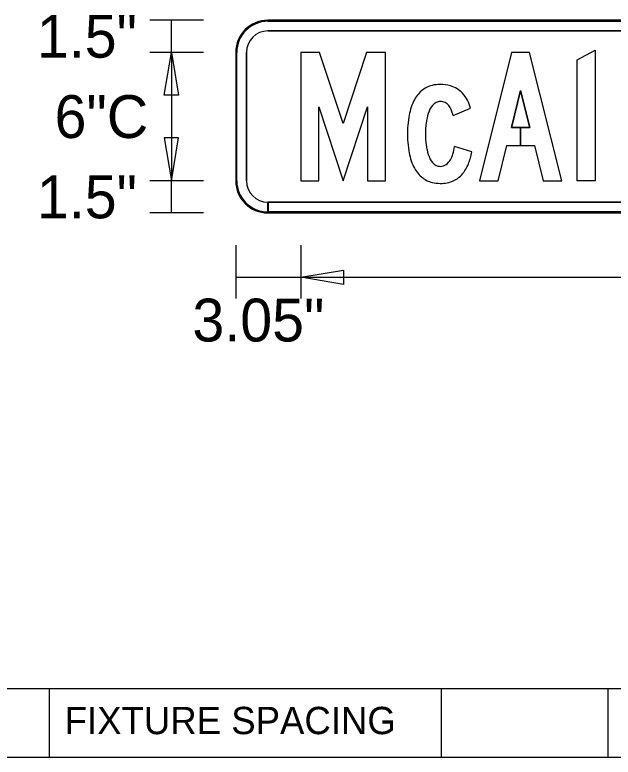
# Model space of a CAD drawing. Extents: x -875 to -645, y -2221 to -2162.
# Drawn here: x -774.222 to -771.896, y -2206.764 to -2203.876 of the extents above; entities that cross this region are included whole.
import ezdxf

# ---------------------------------------------------------------- set-up
doc = ezdxf.new("R2010")
doc.units = 0
for name, color, linetype in [('PlotBorder_dp', 7, 'Continuous'), ('SheetBorder_dp', 7, 'Continuous'), ('SheetLines_dp', 7, 'Continuous'), ('SheetLinesMisc2_dp', 7, 'Continuous'), ('TextMinor', 7, 'Continuous')]:
    doc.layers.add(name, color=color, linetype=linetype)

msp = doc.modelspace()

# ---------------------------------------------------------------- linework, layer by layer
at = {"layer": 'PlotBorder_dp'}
for p, q in [((-769.4881, -2203.8965), (-773.2381, -2203.8965)), ((-773.2381, -2203.9381), (-769.4881, -2203.9381)), ((-773.3631, -2204.0215), (-773.3631, -2204.5215)), ((-773.3215, -2204.5215), (-773.3215, -2204.0215)), ((-772.5183, -2204.2671), (-772.4509, -2204.2387)), ((-772.6906, -2204.2737), (-772.6945, -2204.3064)), ((-772.6945, -2204.3715), (-772.6906, -2204.4042)), ((-772.4456, -2204.4091), (-772.513, -2204.3878)), ((-773.2381, -2204.6465), (-773.2381, -2204.6048)), ((-769.4881, -2204.6048), (-773.2377, -2204.6048)), ((-773.2377, -2204.6048), (-773.2377, -2204.6465)), ((-773.2377, -2204.6465), (-769.4881, -2204.6465))]:
    msp.add_line(p, q, dxfattribs=at)
for points in [[(-772.9456, -2204.5215), (-772.8506, -2204.2336), (-772.8506, -2204.5215), (-772.7806, -2204.5215), (-772.7806, -2204.0215), (-772.8543, -2204.0215), (-772.9456, -2204.2981), (-773.0369, -2204.0215), (-773.1106, -2204.0215), (-773.1106, -2204.5215), (-773.0406, -2204.5215), (-773.0406, -2204.2336)], [(-772.2556, -2204.314), (-772.2916, -2204.314), (-772.2556, -2204.1701), (-772.2197, -2204.314), (-772.2556, -2204.314), (-772.2556, -2204.384), (-772.2022, -2204.384), (-772.1678, -2204.5215), (-772.0956, -2204.5215), (-772.2206, -2204.0215), (-772.2906, -2204.0215), (-772.4156, -2204.5215), (-772.3435, -2204.5215), (-772.3091, -2204.384), (-772.2556, -2204.384)], [(-772.0356, -2204.0513), (-771.9656, -2204.0127), (-771.9656, -2204.5215), (-772.0356, -2204.5215)]]:
    msp.add_lwpolyline(points, close=True, dxfattribs=at)
for centre, radius, start, end in [((-773.2381, -2204.0215), 0.125, 90, 180), ((-773.2381, -2204.0215), 0.0833, 90, 180), ((-772.568, -2204.2819), 0.1354, 90, 103.3083), ((-772.568, -2204.2945), 0.148, 74.6087, 90), ((-772.5636, -2204.262), 0.1192, 130.5312, 155.0073), ((-772.5761, -2204.2474), 0.1, 103.3083, 130.5312), ((-772.5552, -2204.2482), 0.1, 42.4662, 74.6087), ((-772.5766, -2204.2677), 0.1289, 13.0001, 42.4662), ((-772.4682, -2204.3077), 0.225, 154.7275, 171.3047), ((-772.5576, -2204.265), 0.0553, 119.0107, 156.2962), ((-772.568, -2204.2495), 0.0367, 90, 116.5721), ((-772.568, -2204.2574), 0.0447, 77.0877, 90), ((-772.5659, -2204.2512), 0.0382, 50.7088, 78.1008), ((-772.5758, -2204.2616), 0.0525, 28.6423, 49.51), ((-772.4677, -2204.3086), 0.1552, 154.8839, 168.1643), ((-772.6259, -2204.2895), 0.1099, 11.748, 28.8544), ((-772.3749, -2204.3281), 0.25, 168.1643, 172.5576), ((-772.2219, -2204.339), 0.4737, 176.0579, 180), ((-772.2914, -2204.339), 0.3343, 172.5576, 180), ((-772.2219, -2204.339), 0.4737, 180, 183.9421), ((-772.2914, -2204.339), 0.3343, 180, 187.4424), ((-772.4682, -2204.3702), 0.225, 188.6953, 205.2725), ((-772.3749, -2204.3499), 0.25, 187.4424, 191.8357), ((-772.4677, -2204.3693), 0.1552, 191.8357, 205.1161), ((-772.6947, -2204.3646), 0.1832, 343.1877, 352.722), ((-772.5576, -2204.413), 0.0553, 203.7038, 240.9893), ((-772.5911, -2204.3993), 0.0741, 308.3752, 345.7436), ((-772.6864, -2204.3656), 0.2447, 338.343, 349.7655), ((-772.568, -2204.4285), 0.0367, 243.4279, 270), ((-772.568, -2204.4282), 0.037, 270, 308.0074), ((-772.5915, -2204.4035), 0.1425, 320.1081, 338.4281), ((-772.5636, -2204.4159), 0.1192, 204.9927, 229.4688), ((-772.5593, -2204.4293), 0.1012, 294.4184, 319.6313), ((-773.2381, -2204.5215), 0.125, 180, 270), ((-773.2381, -2204.5215), 0.0833, 180, 270), ((-772.5761, -2204.4305), 0.1, 229.4688, 256.6917), ((-772.5599, -2204.4283), 0.1024, 280.7287, 294.4908), ((-772.568, -2204.396), 0.1354, 256.6917, 270), ((-772.568, -2204.3875), 0.144, 269.9997, 280.8647)]:
    msp.add_arc(centre, radius, start, end, dxfattribs=at)
at = {"layer": 'SheetBorder_dp'}
for p, q in [((-769.4881, -2203.8965), (-773.2381, -2203.8965)), ((-769.4881, -2203.8965), (-773.2381, -2203.8965)), ((-769.4881, -2203.8965), (-773.2381, -2203.8965)), ((-773.2381, -2203.9006), (-769.4881, -2203.9006)), ((-773.2381, -2203.9381), (-769.4881, -2203.9381)), ((-773.3631, -2204.0215), (-773.3631, -2204.5215)), ((-773.3631, -2204.0215), (-773.3631, -2204.5215)), ((-773.3631, -2204.0215), (-773.3631, -2204.5215)), ((-773.359, -2204.5215), (-773.359, -2204.0215)), ((-773.3215, -2204.5215), (-773.3215, -2204.0215)), ((-772.5183, -2204.2671), (-772.4509, -2204.2387)), ((-772.6906, -2204.2737), (-772.6945, -2204.3064)), ((-772.6945, -2204.3715), (-772.6906, -2204.4042)), ((-772.4456, -2204.4091), (-772.513, -2204.3878)), ((-773.2381, -2204.6465), (-773.2381, -2204.6048)), ((-769.4881, -2204.6048), (-773.2377, -2204.6048)), ((-773.2377, -2204.6048), (-773.2377, -2204.6465)), ((-773.2381, -2204.6465), (-773.2381, -2204.6423)), ((-769.4881, -2204.6423), (-773.2381, -2204.6423)), ((-773.2381, -2204.6423), (-773.2381, -2204.6465)), ((-773.2381, -2204.6465), (-769.4881, -2204.6465)), ((-773.2381, -2204.6465), (-769.4881, -2204.6465)), ((-773.2377, -2204.6465), (-769.4881, -2204.6465))]:
    msp.add_line(p, q, dxfattribs=at)
for points in [[(-772.9456, -2204.5215), (-772.8506, -2204.2336), (-772.8506, -2204.5215), (-772.7806, -2204.5215), (-772.7806, -2204.0215), (-772.8543, -2204.0215), (-772.9456, -2204.2981), (-773.0369, -2204.0215), (-773.1106, -2204.0215), (-773.1106, -2204.5215), (-773.0406, -2204.5215), (-773.0406, -2204.2336)], [(-772.2556, -2204.314), (-772.2916, -2204.314), (-772.2556, -2204.1701), (-772.2197, -2204.314), (-772.2556, -2204.314), (-772.2556, -2204.384), (-772.2022, -2204.384), (-772.1678, -2204.5215), (-772.0956, -2204.5215), (-772.2206, -2204.0215), (-772.2906, -2204.0215), (-772.4156, -2204.5215), (-772.3435, -2204.5215), (-772.3091, -2204.384), (-772.2556, -2204.384)], [(-772.0356, -2204.0513), (-771.9656, -2204.0127), (-771.9656, -2204.5215), (-772.0356, -2204.5215)]]:
    msp.add_lwpolyline(points, close=True, dxfattribs=at)
for centre, radius, start, end in [((-773.2381, -2204.0215), 0.125, 90, 180), ((-773.2381, -2204.0215), 0.125, 90, 180), ((-773.2381, -2204.0215), 0.125, 90, 180), ((-773.2381, -2204.0215), 0.1208, 90, 180), ((-773.2381, -2204.0215), 0.0833, 90, 180), ((-772.568, -2204.2819), 0.1354, 90, 103.3083), ((-772.568, -2204.2945), 0.148, 74.6087, 90), ((-772.5636, -2204.262), 0.1192, 130.5312, 155.0073), ((-772.5761, -2204.2474), 0.1, 103.3083, 130.5312), ((-772.5552, -2204.2482), 0.1, 42.4662, 74.6087), ((-772.5766, -2204.2677), 0.1289, 13.0001, 42.4662), ((-772.4682, -2204.3077), 0.225, 154.7275, 171.3047), ((-772.5576, -2204.265), 0.0553, 119.0107, 156.2962), ((-772.568, -2204.2495), 0.0367, 90, 116.5721), ((-772.568, -2204.2574), 0.0447, 77.0877, 90), ((-772.5659, -2204.2512), 0.0382, 50.7088, 78.1008), ((-772.5758, -2204.2616), 0.0525, 28.6423, 49.51), ((-772.4677, -2204.3086), 0.1552, 154.8839, 168.1643), ((-772.6259, -2204.2895), 0.1099, 11.748, 28.8544), ((-772.3749, -2204.3281), 0.25, 168.1643, 172.5576), ((-772.2219, -2204.339), 0.4737, 176.0579, 180), ((-772.2914, -2204.339), 0.3343, 172.5576, 180), ((-772.2219, -2204.339), 0.4737, 180, 183.9421), ((-772.2914, -2204.339), 0.3343, 180, 187.4424), ((-772.4682, -2204.3702), 0.225, 188.6953, 205.2725), ((-772.3749, -2204.3499), 0.25, 187.4424, 191.8357), ((-772.4677, -2204.3693), 0.1552, 191.8357, 205.1161), ((-772.6947, -2204.3646), 0.1832, 343.1877, 352.722), ((-772.5576, -2204.413), 0.0553, 203.7038, 240.9893), ((-772.5911, -2204.3993), 0.0741, 308.3752, 345.7436), ((-772.6864, -2204.3656), 0.2447, 338.343, 349.7655), ((-772.568, -2204.4285), 0.0367, 243.4279, 270), ((-772.568, -2204.4282), 0.037, 270, 308.0074), ((-772.5915, -2204.4035), 0.1425, 320.1081, 338.4281), ((-772.5636, -2204.4159), 0.1192, 204.9927, 229.4688), ((-772.5593, -2204.4293), 0.1012, 294.4184, 319.6313), ((-773.2381, -2204.5215), 0.125, 180, 270), ((-773.2381, -2204.5215), 0.125, 180, 270), ((-773.2381, -2204.5215), 0.125, 180, 270), ((-773.2381, -2204.5215), 0.1208, 180, 270), ((-773.2381, -2204.5215), 0.0833, 180, 270), ((-772.5761, -2204.4305), 0.1, 229.4688, 256.6917), ((-772.5599, -2204.4283), 0.1024, 280.7287, 294.4908), ((-772.568, -2204.396), 0.1354, 256.6917, 270), ((-772.568, -2204.3875), 0.144, 269.9997, 280.8647)]:
    msp.add_arc(centre, radius, start, end, dxfattribs=at)
at = {"layer": 'SheetLines_dp'}
for p, q in [((-769.4881, -2203.8965), (-773.2381, -2203.8965)), ((-769.4881, -2203.9381), (-773.2381, -2203.9381)), ((-773.3631, -2204.0215), (-773.3631, -2204.5215)), ((-773.3215, -2204.0215), (-773.3215, -2204.5215)), ((-772.5183, -2204.2671), (-772.4509, -2204.2387)), ((-772.6906, -2204.2737), (-772.6945, -2204.3064)), ((-772.6945, -2204.3715), (-772.6906, -2204.4042)), ((-772.4456, -2204.4091), (-772.513, -2204.3878)), ((-773.2381, -2204.6048), (-769.4881, -2204.6048)), ((-773.2381, -2204.6465), (-769.4881, -2204.6465))]:
    msp.add_line(p, q, dxfattribs=at)
for points in [[(-772.9456, -2204.5215), (-772.8506, -2204.2336), (-772.8506, -2204.5215), (-772.7806, -2204.5215), (-772.7806, -2204.0215), (-772.8543, -2204.0215), (-772.9456, -2204.2981), (-773.0369, -2204.0215), (-773.1106, -2204.0215), (-773.1106, -2204.5215), (-773.0406, -2204.5215), (-773.0406, -2204.2336)], [(-772.3091, -2204.384), (-772.2022, -2204.384), (-772.1678, -2204.5215), (-772.0956, -2204.5215), (-772.2206, -2204.0215), (-772.2906, -2204.0215), (-772.4156, -2204.5215), (-772.3435, -2204.5215)], [(-772.0356, -2204.0513), (-771.9656, -2204.0127), (-771.9656, -2204.5215), (-772.0356, -2204.5215)], [(-772.2197, -2204.314), (-772.2556, -2204.1701), (-772.2916, -2204.314)]]:
    msp.add_lwpolyline(points, close=True, dxfattribs=at)
for centre, radius, start, end in [((-773.2381, -2204.0215), 0.125, 90, 180), ((-773.2381, -2204.0215), 0.0833, 90, 180), ((-772.568, -2204.2819), 0.1354, 90, 103.3083), ((-772.568, -2204.2945), 0.148, 74.6087, 90), ((-772.5636, -2204.262), 0.1192, 130.5312, 155.0073), ((-772.5761, -2204.2474), 0.1, 103.3083, 130.5312), ((-772.5552, -2204.2482), 0.1, 42.4662, 74.6087), ((-772.5766, -2204.2677), 0.1289, 13.0001, 42.4662), ((-772.4682, -2204.3077), 0.225, 154.7275, 171.3047), ((-772.5576, -2204.265), 0.0553, 119.0107, 156.2962), ((-772.568, -2204.2495), 0.0367, 90, 116.5721), ((-772.568, -2204.2574), 0.0447, 77.0877, 90), ((-772.5659, -2204.2512), 0.0382, 50.7088, 78.1008), ((-772.5758, -2204.2616), 0.0525, 28.6423, 49.51), ((-772.4677, -2204.3086), 0.1552, 154.8839, 168.1643), ((-772.6259, -2204.2895), 0.1099, 11.748, 28.8544), ((-772.3749, -2204.3281), 0.25, 168.1643, 172.5576), ((-772.2219, -2204.339), 0.4737, 176.0579, 180), ((-772.2914, -2204.339), 0.3343, 172.5576, 180), ((-772.2219, -2204.339), 0.4737, 180, 183.9421), ((-772.2914, -2204.339), 0.3343, 180, 187.4424), ((-772.4682, -2204.3702), 0.225, 188.6953, 205.2725), ((-772.3749, -2204.3499), 0.25, 187.4424, 191.8357), ((-772.4677, -2204.3693), 0.1552, 191.8357, 205.1161), ((-772.6947, -2204.3646), 0.1832, 343.1877, 352.722), ((-772.5576, -2204.413), 0.0553, 203.7038, 240.9893), ((-772.5911, -2204.3993), 0.0741, 308.3752, 345.7436), ((-772.6864, -2204.3656), 0.2447, 338.343, 349.7655), ((-772.568, -2204.4285), 0.0367, 243.4279, 270), ((-772.568, -2204.4282), 0.037, 270, 308.0074), ((-772.5915, -2204.4035), 0.1425, 320.1081, 338.4281), ((-772.5636, -2204.4159), 0.1192, 204.9927, 229.4688), ((-772.5593, -2204.4293), 0.1012, 294.4184, 319.6313), ((-773.2381, -2204.5215), 0.125, 180, 270), ((-773.2381, -2204.5215), 0.0833, 180, 270), ((-772.5761, -2204.4305), 0.1, 229.4688, 256.6917), ((-772.5599, -2204.4283), 0.1024, 280.7287, 294.4908), ((-772.568, -2204.396), 0.1354, 256.6917, 270), ((-772.568, -2204.3875), 0.144, 269.9997, 280.8647)]:
    msp.add_arc(centre, radius, start, end, dxfattribs=at)
at = {"layer": 'SheetLinesMisc2_dp'}
for p, q in [((-776.4796, -2206.4967), (-766.2466, -2206.4967)), ((-774.0889, -2206.4967), (-774.0889, -2206.7638)), ((-772.5652, -2206.4967), (-772.5652, -2206.7638)), ((-771.9166, -2206.4967), (-771.9166, -2206.7638)), ((-776.4796, -2206.7638), (-766.2466, -2206.7638))]:
    msp.add_line(p, q, dxfattribs=at)
at = {"layer": 'TextMinor'}
for p, q in [((-773.4881, -2203.8965), (-773.6965, -2203.8965)), ((-773.6131, -2204.0215), (-773.6131, -2203.8965)), ((-773.4881, -2204.0215), (-773.6965, -2204.0215)), ((-773.4881, -2204.0215), (-773.6965, -2204.0215)), ((-773.6131, -2204.0215), (-773.6131, -2204.5215)), ((-773.4881, -2204.5215), (-773.6965, -2204.5215)), ((-773.4881, -2204.5215), (-773.6965, -2204.5215)), ((-773.6131, -2204.6465), (-773.6131, -2204.5215)), ((-773.4881, -2204.6465), (-773.6965, -2204.6465)), ((-773.3631, -2204.7715), (-773.3631, -2204.9798)), ((-773.1106, -2204.7715), (-773.1106, -2204.9798)), ((-773.1106, -2204.7715), (-773.1106, -2204.9798)), ((-773.3631, -2204.8965), (-773.1106, -2204.8965)), ((-773.1106, -2204.8965), (-769.6156, -2204.8965))]:
    msp.add_line(p, q, dxfattribs=at)
for points in [[(-773.6131, -2204.0215), (-773.5853, -2204.1881), (-773.6409, -2204.1881)], [(-773.6131, -2204.5215), (-773.5853, -2204.3548), (-773.6409, -2204.3548)], [(-773.1106, -2204.8965), (-772.944, -2204.8687), (-772.944, -2204.9243)]]:
    msp.add_lwpolyline(points, close=True, dxfattribs=at)

# ---------------------------------------------------------------- texts
for s, height, p in [('1.5"', 0.16667, (-774.1359, -2204.0423)), ('6"C', 0.16667, (-774.0673, -2204.3548)), ('1.5"', 0.16667, (-774.1359, -2204.6673)), ('3.05"', 0.16667, (-773.5314, -2205.1465)), ('FIXTURE SPACING', 0.106291, (-774.0281, -2206.6743))]:
    msp.add_text(s, height=height, dxfattribs=at).set_placement(p)

doc.saveas('drawing.dxf')
